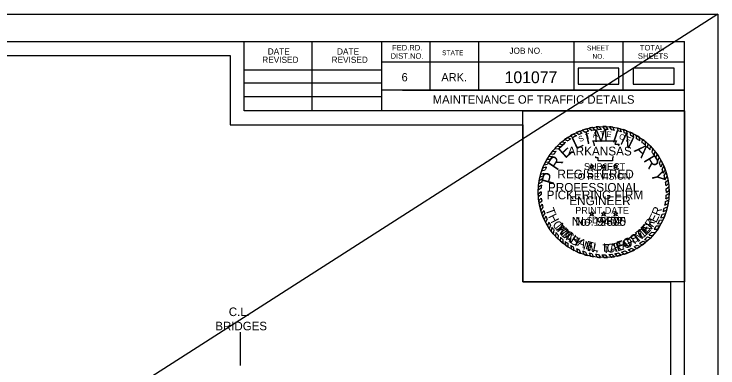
# Model space of a CAD drawing. Extents: x 13528 to 25043, y 7635 to 10612.
# Drawn here: x 22933 to 23433, y 10360 to 10612 of the extents above; entities that cross this region are included whole.
import ezdxf

# ---------------------------------------------------------------- set-up
doc = ezdxf.new("R2010")
doc.units = 0
for name, color, linetype in [('Default', 7, 'Continuous'), ('R_Border Notes', 7, 'Continuous'), ('R_Draft', 7, 'Continuous'), ('R_Revision Date Text', 7, 'Continuous'), ('STAMP_PE_CRAFTON', 7, 'Continuous'), ('STAMP_PE_FOSTER', 7, 'Continuous'), ('STAMP_PE_SEAL-INFO', 7, 'Continuous'), ('STAMP_PE_TAEGTMEYER', 7, 'Continuous'), ('STAMP_PE_TXT', 7, 'Continuous')]:
    doc.layers.add(name, color=color, linetype=linetype)

msp = doc.modelspace()

# ---------------------------------------------------------------- linework, layer by layer
at = {"layer": 'Default'}
for p, q in [((23433.27, 10611.55), (21766.57, 9544.86)), ((23093.63, 10361.47), (23093.63, 10385.3))]:
    msp.add_line(p, q, dxfattribs=at)
for points in [[(23333.73, 10561.6), (23362.89, 10561.6), (23362.89, 10573.15), (23333.73, 10573.15)], [(23372.93, 10561.6), (23402.09, 10561.6), (23402.09, 10573.15), (23372.93, 10573.15)]]:
    msp.add_lwpolyline(points, close=True, dxfattribs=at)
at = {"layer": 'R_Draft'}
for p, q in [((21828.61, 10592.07), (23409.51, 10592.07)), ((23096.31, 10542.67), (23096.31, 10592.07)), ((23144.71, 10542.67), (23144.71, 10592.07)), ((23194.01, 10592.07), (23194.01, 10542.67)), ((23228.21, 10592.07), (23228.21, 10557.37)), ((23262.91, 10592.07), (23262.91, 10557.37)), ((23330.81, 10592.07), (23330.81, 10557.37)), ((23365.51, 10592.07), (23365.51, 10557.37)), ((23409.51, 9564.77), (23409.51, 10592.07)), ((23409.51, 10577.37), (23194.01, 10577.37)), ((23409.51, 10577.47), (23409.51, 10577.47)), ((23096.31, 10571.97), (23194.01, 10571.97)), ((23096.31, 10562.67), (23194.01, 10562.67)), ((23409.51, 10557.37), (23194.01, 10557.37)), ((23208.81, 10557.37), (23409.51, 10557.37)), ((23096.31, 10552.97), (23194.01, 10552.97)), ((23409.51, 10542.67), (23096.31, 10542.67))]:
    msp.add_line(p, q, dxfattribs=at)
at = {"layer": 'R_Revision Date Text'}
for points in [[(21766.57, 10611.55), (23433.27, 10611.55), (23433.27, 9544.86), (21766.57, 9544.86)], [(23399.51, 10088.42), (21838.61, 10088.42), (21838.61, 10582.07), (23086.31, 10582.07), (23086.31, 10532.67), (23174.01, 10532.67), (23294.51, 10532.67), (23294.51, 10421.01), (23399.51, 10421.01)], [(21838.61, 10582.07), (23086.31, 10582.07), (23086.31, 10532.67), (23174.01, 10532.67), (23294.51, 10532.67), (23294.51, 10421.01), (23399.51, 10421.01), (23399.51, 9574.77), (21838.61, 9574.77)], [(23294.51, 10542.67), (23409.51, 10542.67), (23409.51, 10421.01), (23294.51, 10421.01)]]:
    msp.add_lwpolyline(points, close=True, dxfattribs=at)
at = {"layer": 'STAMP_PE_SEAL-INFO'}
for p, q in [((23341.7, 10530.35), (23343.48, 10528.63)), ((23344.11, 10530.83), (23345.61, 10528.99)), ((23346.69, 10531.19), (23348.1, 10529.28)), ((23350.37, 10529.42), (23348.81, 10531.39)), ((23352.86, 10529.45), (23351.46, 10531.5)), ((23355.15, 10529.34), (23353.86, 10531.46)), ((23357.68, 10529.09), (23356.21, 10531.31)), ((23359.8, 10528.77), (23358.52, 10531.04)), ((23362.62, 10528.17), (23361.75, 10530.47)), ((23330.37, 10526.17), (23332.69, 10525.05)), ((23332.53, 10527.23), (23334.48, 10525.86)), ((23335.07, 10528.31), (23336.54, 10526.68)), ((23336.81, 10528.95), (23338.71, 10527.42)), ((23339.76, 10529.86), (23341.2, 10528.12)), ((23364.62, 10527.63), (23363.83, 10529.98)), ((23366.88, 10526.9), (23366.18, 10529.29)), ((23368.97, 10526.1), (23368.25, 10528.58)), ((23371.28, 10525.07), (23370.77, 10527.56)), ((23373.51, 10523.92), (23373.07, 10526.47)), ((23375.45, 10522.79), (23375.25, 10525.29)), ((23322.21, 10520.73), (23324.86, 10520.23)), ((23324.1, 10522.37), (23326.38, 10521.34)), ((23326.2, 10523.7), (23328.41, 10522.69)), ((23328.13, 10524.92), (23330.29, 10523.81)), ((23344.37, 10521.34), (23361.09, 10521.34)), ((23344.98, 10519.81), (23344.37, 10521.34)), ((23361.09, 10521.34), (23359.97, 10518.88)), ((23377.62, 10521.36), (23377.46, 10523.93)), ((23379.42, 10520.02), (23379.59, 10522.46)), ((23381.66, 10518.16), (23381.75, 10520.78)), ((23317.2, 10515.89), (23319.81, 10515.7)), ((23318.82, 10517.61), (23321.54, 10517.41)), ((23320.49, 10519.23), (23322.79, 10518.54)), ((23345.5, 10518.32), (23344.98, 10519.81)), ((23345.54, 10517.75), (23345.5, 10518.32)), ((23359.97, 10518.88), (23363.13, 10518.88)), ((23363.13, 10518.88), (23362.41, 10517.75)), ((23383.22, 10516.7), (23383.56, 10519.19)), ((23385.01, 10514.83), (23385.35, 10517.46)), ((23386.38, 10513.25), (23387.06, 10515.61)), ((23312.91, 10510.27), (23315.49, 10510.44)), ((23314.08, 10511.99), (23316.61, 10511.96)), ((23315.48, 10513.84), (23318.22, 10513.95)), ((23346.49, 10509.2), (23346.36, 10510.29)), ((23358.68, 10510.29), (23358.29, 10508.74)), ((23388, 10511.17), (23388.68, 10513.66)), ((23389.1, 10509.59), (23389.99, 10511.91)), ((23310.53, 10506.15), (23313.02, 10506.47)), ((23311.68, 10508.26), (23314.13, 10508.36)), ((23348.06, 10509.2), (23346.49, 10509.2)), ((23348.06, 10507.05), (23348.06, 10509.2)), ((23358.21, 10507.05), (23348.06, 10507.05)), ((23358.29, 10508.74), (23358.21, 10507.05)), ((23390.64, 10507.1), (23391.56, 10509.56)), ((23391.64, 10505.27), (23392.77, 10507.49)), ((23392.79, 10502.85), (23393.93, 10505.28)), ((23307.92, 10500.01), (23310.34, 10500.69)), ((23308.67, 10502.04), (23311.19, 10502.77)), ((23309.59, 10504.2), (23312.1, 10504.72)), ((23393.5, 10501.17), (23394.82, 10503.33)), ((23394.47, 10498.42), (23395.82, 10500.79)), ((23306.61, 10495.46), (23308.96, 10496.42)), ((23307.13, 10497.49), (23309.52, 10498.34)), ((23395.01, 10496.6), (23396.48, 10498.86)), ((23395.67, 10493.8), (23397.27, 10496.04)), ((23308, 10491.93), (23305.77, 10490.82)), ((23308.43, 10494.22), (23306.1, 10492.98)), ((23396.02, 10491.9), (23397.79, 10493.67)), ((23396.35, 10489.36), (23398.21, 10491.04)), ((23307.53, 10487.63), (23305.42, 10486.34)), ((23307.71, 10489.75), (23305.52, 10488.35)), ((23396.51, 10487.27), (23398.46, 10488.73)), ((23396.58, 10484.68), (23398.6, 10486.29)), ((23307.44, 10485.16), (23305.42, 10483.48)), ((23307.48, 10483.13), (23305.52, 10481.5)), ((23307.64, 10480.65), (23305.79, 10478.87)), ((23396.32, 10480.12), (23398.49, 10481.4)), ((23396.52, 10482.65), (23398.61, 10484.04)), ((23307.9, 10478.5), (23306.13, 10476.64)), ((23308.29, 10476.21), (23306.6, 10474.37)), ((23395.62, 10475.68), (23397.89, 10476.66)), ((23396.07, 10478.18), (23398.28, 10479.28)), ((23308.76, 10474.11), (23307.2, 10472.04)), ((23309.38, 10471.88), (23307.91, 10469.79)), ((23394.34, 10470.95), (23396.79, 10471.95)), ((23395.08, 10473.42), (23397.43, 10474.43)), ((23310.09, 10469.76), (23308.68, 10467.7)), ((23310.92, 10467.63), (23309.61, 10465.52)), ((23311.78, 10465.71), (23310.64, 10463.41)), ((23392.6, 10466.48), (23395.04, 10466.96)), ((23393.67, 10469.05), (23396.08, 10469.7)), ((23312.95, 10463.42), (23312, 10460.97)), ((23314.13, 10461.4), (23313.21, 10459.05)), ((23389.57, 10460.9), (23391.96, 10460.87)), ((23390.43, 10462.3), (23392.94, 10462.57)), ((23391.79, 10464.8), (23394.23, 10465.14)), ((23315.14, 10459.85), (23314.59, 10457.09)), ((23316.54, 10457.89), (23316.04, 10455.24)), ((23318.06, 10456.01), (23317.63, 10453.41)), ((23386.33, 10456.46), (23388.64, 10456.06)), ((23387.87, 10458.43), (23390.4, 10458.44)), ((23319.58, 10454.32), (23319.27, 10451.71)), ((23321.19, 10452.69), (23321.04, 10450.05)), ((23322.91, 10451.13), (23322.89, 10448.48)), ((23381.12, 10451.14), (23383.47, 10450.49)), ((23383.14, 10453), (23385.35, 10452.31)), ((23384.42, 10454.29), (23386.8, 10453.87)), ((23324.71, 10449.66), (23324.8, 10447.03)), ((23326.4, 10448.41), (23326.58, 10445.82)), ((23328.54, 10447), (23328.84, 10444.44)), ((23330.29, 10445.97), (23330.75, 10443.4)), ((23373.67, 10445.94), (23375.75, 10444.77)), ((23375.74, 10447.16), (23377.99, 10446.18)), ((23377.46, 10448.3), (23379.65, 10447.35)), ((23379.76, 10450.01), (23382.1, 10449.29)), ((23332.7, 10444.72), (23333.48, 10442.11)), ((23334.56, 10443.88), (23335.42, 10441.32)), ((23337.02, 10442.91), (23338.07, 10440.41)), ((23339.07, 10442.24), (23340.2, 10439.79)), ((23341.61, 10441.55), (23342.67, 10439.22)), ((23343.6, 10441.12), (23344.83, 10438.83)), ((23346.1, 10440.71), (23347.3, 10438.51)), ((23348.28, 10440.47), (23349.65, 10438.33)), ((23350.7, 10440.34), (23352.22, 10438.27)), ((23353, 10440.33), (23354.72, 10438.35)), ((23355.6, 10440.46), (23357.22, 10438.56)), ((23357.79, 10440.69), (23359.65, 10438.9)), ((23360.01, 10441.04), (23361.95, 10439.35)), ((23362.47, 10441.56), (23364.36, 10439.94)), ((23364.77, 10442.19), (23366.85, 10440.7)), ((23367.24, 10443), (23369.45, 10441.66)), ((23369.33, 10443.82), (23371.45, 10442.52)), ((23371.63, 10444.87), (23374.05, 10443.81))]:
    msp.add_line(p, q, dxfattribs=at)
msp.add_circle((23352.01, 10484.89), 46.61, dxfattribs=at)
for radius, start, end in [(46.61, 99.7525, 102.7765), (46.61, 93.9381, 96.5517), (46.61, 87.7298, 90.6707), (46.61, 81.9732, 84.8236), (46.61, 75.3125, 77.9426), (46.61, 117.6544, 120.8099), (46.61, 111.3124, 114.7026), (44.57, 110.3086, 113.1659), (46.61, 105.2339, 109.0352), (44.57, 104.0352, 107.3615), (44.57, 98.258, 101.0329), (44.57, 92.1102, 95.0367), (44.57, 85.9628, 88.9097), (44.57, 79.9264, 82.696), (44.57, 73.5575, 76.2314), (46.61, 69.6061, 72.3058), (44.57, 67.6248, 70.504), (46.61, 63.1329, 66.2704), (46.61, 56.9003, 60.0942), (46.61, 129.7326, 132.5376), (46.61, 123.6199, 126.5906), (44.57, 121.9746, 125.11), (44.57, 115.6869, 119.1583), (44.57, 61.1558, 64.3784), (44.57, 54.9238, 58.2702), (46.61, 50.3492, 53.7159), (46.61, 135.4021, 138.3031), (44.57, 133.1331, 136.2562), (44.57, 127.5297, 130.9683), (44.57, 48.3016, 52.0395), (44.57, 42.2212, 45.5512), (46.61, 44.3405, 47.3929), (46.61, 38.1247, 41.2316), (46.61, 147.0072, 149.899), (46.61, 141.6056, 144.4486), (44.57, 145.0197, 148.2104), (44.57, 139.301, 142.5873), (44.57, 36.135, 39.5311), (46.61, 31.9614, 35.4294), (46.61, 152.864, 155.5189), (44.57, 151.0315, 153.573), (44.57, 29.9032, 33.6645), (44.57, 23.7732, 27.2211), (46.61, 25.9391, 29.0125), (46.61, 158.4077, 161.0701), (44.57, 156.3402, 159.2319), (44.57, 17.6802, 21.4251), (46.61, 19.9538, 23.3141), (46.61, 164.3068, 166.894), (44.57, 162.4331, 165.0013), (44.57, 11.5444, 15.2364), (46.61, 13.8421, 17.4447), (46.61, 170.0003, 172.6878), (44.57, 167.9048, 170.9039), (44.57, 5.7599, 9.0606), (46.61, 7.5852, 10.8621), (46.61, 175.7409, 178.2066), (44.57, 173.73, 176.4734), (44.57, 359.7329, 3.0639), (46.61, 1.7215, 4.7268), (46.61, 181.7251, 184.1626), (44.57, 179.6454, 182.2633), (44.57, 185.4539, 188.234), (44.57, 353.8632, 357.1274), (46.61, 355.7156, 358.9569), (46.61, 187.4204, 190.1927), (44.57, 191.2274, 193.9858), (44.57, 348.0778, 351.3435), (46.61, 349.8305, 353.0885), (46.61, 193.0369, 195.9973), (44.57, 196.9675, 199.8353), (44.57, 341.777, 345.0925), (46.61, 343.8925, 347.035), (46.61, 198.8967, 201.6281), (46.61, 204.5479, 207.4328), (44.57, 202.7761, 205.4791), (44.57, 335.6038, 339.1858), (46.61, 337.3837, 340.9933), (46.61, 210.8636, 213.6571), (44.57, 208.7883, 211.7934), (44.57, 323.5851, 327.4407), (46.61, 325.4405, 328.9872), (44.57, 329.5549, 333.2076), (46.61, 331.4037, 334.9332), (46.61, 216.6115, 219.491), (44.57, 214.1838, 217.2747), (44.57, 220.3909, 223.3056), (44.57, 316.6531, 320.3711), (46.61, 318.2846, 321.8043), (46.61, 222.48, 225.3801), (44.57, 226.2494, 229.2407), (44.57, 310.7744, 314.3161), (46.61, 312.4518, 315.6633), (46.61, 228.3665, 231.348), (44.57, 232.229, 234.9336), (46.61, 234.295, 236.9452), (44.57, 238.2223, 240.8353), (44.57, 299.0768, 302.1724), (46.61, 300.621, 303.8703), (44.57, 304.823, 308.5143), (46.61, 306.3721, 310.208), (46.61, 240.1977, 242.8613), (44.57, 244.3204, 246.9486), (46.61, 246.576, 249.1558), (44.57, 250.3491, 253.1216), (46.61, 252.5967, 255.3252), (44.57, 256.505, 259.1192), (44.57, 262.3783, 265.2012), (44.57, 268.3215, 271.277), (44.57, 274.6157, 277.4486), (44.57, 280.3459, 283.5814), (44.57, 286.6423, 289.9783), (46.61, 288.5709, 291.9733), (44.57, 292.8745, 296.1185), (46.61, 294.6481, 298.2166), (46.61, 258.4433, 261.1398), (46.61, 264.1978, 267.1009), (46.61, 270.2548, 273.3361), (46.61, 276.4239, 279.4357), (46.61, 282.3199, 285.3702)]:
    msp.add_arc((23352.01, 10484.89), radius, start, end, dxfattribs=at)
at = {"layer": 'STAMP_PE_TXT'}
for p, q in [((23342.91, 10502.74), (23341.91, 10503.46)), ((23341.91, 10503.46), (23343.14, 10503.46)), ((23342.53, 10501.58), (23342.91, 10502.74)), ((23343.52, 10502.3), (23342.53, 10501.58)), ((23343.14, 10503.46), (23343.52, 10504.63)), ((23343.52, 10504.63), (23343.9, 10503.46)), ((23344.51, 10501.58), (23343.52, 10502.3)), ((23343.9, 10503.46), (23345.12, 10503.46)), ((23345.12, 10503.46), (23344.13, 10502.74)), ((23344.13, 10502.74), (23344.51, 10501.58)), ((23351.4, 10502.74), (23350.4, 10503.46)), ((23350.4, 10503.46), (23351.63, 10503.46)), ((23351.02, 10501.58), (23351.4, 10502.74)), ((23352.01, 10502.3), (23351.02, 10501.58)), ((23351.63, 10503.46), (23352.01, 10504.63)), ((23352.01, 10504.63), (23352.39, 10503.46)), ((23353, 10501.58), (23352.01, 10502.3)), ((23352.39, 10503.46), (23353.61, 10503.46)), ((23353.61, 10503.46), (23352.62, 10502.74)), ((23352.62, 10502.74), (23353, 10501.58)), ((23359.89, 10502.74), (23358.89, 10503.46)), ((23358.89, 10503.46), (23360.12, 10503.46)), ((23359.51, 10501.58), (23359.89, 10502.74)), ((23360.5, 10502.3), (23359.51, 10501.58)), ((23360.12, 10503.46), (23360.5, 10504.63)), ((23360.5, 10504.63), (23360.88, 10503.46)), ((23361.49, 10501.58), (23360.5, 10502.3)), ((23360.88, 10503.46), (23362.1, 10503.46)), ((23362.1, 10503.46), (23361.11, 10502.74)), ((23361.11, 10502.74), (23361.49, 10501.58)), ((23343.14, 10469.93), (23343.52, 10471.09)), ((23343.52, 10471.09), (23343.9, 10469.93)), ((23351.63, 10469.93), (23352.01, 10471.09)), ((23352.01, 10471.09), (23352.39, 10469.93)), ((23360.12, 10469.93), (23360.5, 10471.09)), ((23360.5, 10471.09), (23360.88, 10469.93)), ((23342.91, 10469.21), (23341.91, 10469.93)), ((23341.91, 10469.93), (23343.14, 10469.93)), ((23342.53, 10468.04), (23342.91, 10469.21)), ((23343.52, 10468.76), (23342.53, 10468.04)), ((23344.51, 10468.04), (23343.52, 10468.76)), ((23343.9, 10469.93), (23345.12, 10469.93)), ((23345.12, 10469.93), (23344.13, 10469.21)), ((23344.13, 10469.21), (23344.51, 10468.04)), ((23351.4, 10469.21), (23350.4, 10469.93)), ((23350.4, 10469.93), (23351.63, 10469.93)), ((23351.02, 10468.04), (23351.4, 10469.21)), ((23352.01, 10468.76), (23351.02, 10468.04)), ((23353, 10468.04), (23352.01, 10468.76)), ((23352.39, 10469.93), (23353.61, 10469.93)), ((23353.61, 10469.93), (23352.62, 10469.21)), ((23352.62, 10469.21), (23353, 10468.04)), ((23359.89, 10469.21), (23358.89, 10469.93)), ((23358.89, 10469.93), (23360.12, 10469.93)), ((23359.51, 10468.04), (23359.89, 10469.21)), ((23360.5, 10468.76), (23359.51, 10468.04)), ((23361.49, 10468.04), (23360.5, 10468.76)), ((23360.88, 10469.93), (23362.1, 10469.93)), ((23362.1, 10469.93), (23361.11, 10469.21)), ((23361.11, 10469.21), (23361.49, 10468.04))]:
    msp.add_line(p, q, dxfattribs=at)

# ---------------------------------------------------------------- texts
at = {"layer": 'Default'}
for s, p in [('C.L. ', (23085.31, 10396.64)), ('BRIDGES', (23075.75, 10386.51))]:
    msp.add_text(s, height=6.1, dxfattribs=at).set_placement(p)
at = {"layer": 'R_Border Notes'}
for s, height, p in [('101077', 8.4, (23281.53, 10562.4)), ('MAINTENANCE OF TRAFFIC DETAILS', 6, (23230.35, 10547.77))]:
    msp.add_text(s, height=height, dxfattribs=at).set_placement(p)
at = {"layer": 'R_Draft'}
for s, height, p in [('DATE', 4.396, (23113, 10582.75)), ('DATE', 4.396, (23162.3, 10582.75)), ('FED.RD.', 3.91, (23201.41, 10585.67)), ('STATE', 3.42, (23237.01, 10582.27)), ('JOB NO.', 4.396, (23284.91, 10583.27)), ('SHEET', 3.42, (23340.11, 10585.67)), ('TOTAL', 3.91, (23377.71, 10585.67)), ('REVISED', 4.396, (23109.1, 10576.85)), ('REVISED', 4.396, (23158.4, 10576.85)), ('DIST.NO.', 3.91, (23200.41, 10579.77)), ('NO.', 3.42, (23344.01, 10579.77)), ('SHEETS', 3.91, (23376.31, 10579.77)), ('6', 5.86, (23208.21, 10563.67)), ('ARK.', 5.861, (23236.51, 10563.67))]:
    msp.add_text(s, height=height, dxfattribs=at).set_placement(p)
at = {"layer": 'STAMP_PE_CRAFTON'}
msp.add_text('No. 12370', height=6.25, dxfattribs=at).set_placement((23329.32, 10460.87))
for s, rotation, p in [('T', 310.7442, (23316.84, 10459.37)), ('N', 49.2411, (23383.42, 10455)), ('O', 317.6422, (23320.17, 10455.32)), ('N', 324.4537, (23324.4, 10451.39)), ('T', 34.1136, (23374.89, 10448.08)), ('O', 41.8391, (23379.18, 10451.09)), ('Y', 331.1686, (23329.57, 10447.81)), ('A', 20.5125, (23365.41, 10443.66)), ('F', 28.7821, (23370.31, 10445.53)), ('N', 347.4752, (23339.84, 10443.23)), ('C', 6.0117, (23354.37, 10441.59)), ('R', 14.8189, (23359.85, 10442.17)), ('.', 356.8926, (23345.99, 10441.85))]:
    msp.add_text(s, height=6.25, rotation=rotation, dxfattribs=at).set_placement(p)
at = {"layer": 'STAMP_PE_FOSTER'}
msp.add_text('No. 9402', height=6.25, dxfattribs=at).set_placement((23331.94, 10460.87))
for s, rotation, p in [('R', 54.5031, (23385.63, 10458.94)), ('M', 308.339, (23317.59, 10460)), ('E', 46.9613, (23382.01, 10454.84)), ('I', 314.1842, (23321.58, 10455.31)), ('C', 319.8733, (23323.35, 10453.54)), ('T', 39.4194, (23377.72, 10451.09)), ('H', 327.7235, (23327.99, 10449.86)), ('A', 335.7276, (23332.9, 10446.95)), ('E', 343.5779, (23338.59, 10444.6)), ('F', 15.8691, (23362.18, 10443.66)), ('O', 23.719, (23367.41, 10445.3)), ('S', 31.7234, (23372.96, 10447.95)), ('L', 350.8115, (23343.88, 10443.21)), ('L', 1.2666, (23351.58, 10442.43)), ('.', 6.8035, (23356.81, 10442.72))]:
    msp.add_text(s, height=6, rotation=rotation, dxfattribs=at).set_placement(p)
at = {"layer": 'STAMP_PE_SEAL-INFO'}
for s, rotation, p in [('I', 12.5248, (23339.7, 10518.82)), ('M', 3.1074, (23345.19, 10520.36)), ('I', 342.3164, (23357.53, 10520.7)), ('N', 333.9382, (23363.06, 10519.33)), ('L', 25.513, (23332.05, 10515.02)), ('E', 42.3578, (23324.64, 10508.37)), ('A', 315.6579, (23373.23, 10514.2)), ('R', 56.2292, (23318.86, 10499.7)), ('R', 301.3831, (23380.07, 10507.63)), ('Y', 283.2593, (23385.52, 10498.7)), ('P', 73.913, (23316.12, 10489.59))]:
    msp.add_text(s, height=9, rotation=rotation, dxfattribs=at).set_placement(p)
for s, height, p in [('SUBJECT', 4.8, (23338.01, 10500.63)), ('TO REVISION', 4.8, (23329.69, 10493.71)), ('PICKERING FIRM', 6.25, (23311.38, 10479.7)), ('PRINT DATE', 4.8, (23331.8, 10469.46)), ('$DATE$', 4.8, (23340.18, 10462.54))]:
    msp.add_text(s, height=height, dxfattribs=at).set_placement(p)
at = {"layer": 'STAMP_PE_TAEGTMEYER'}
for s, rotation, p in [('T', 289.646, (23310.48, 10472.44)), ('R', 69.57, (23391.73, 10467.46)), ('H', 296.7339, (23312.28, 10467.51)), ('Y', 53.9986, (23385.9, 10457.85)), ('E', 63.0984, (23389.24, 10462.55)), ('O', 303.7708, (23315.24, 10461.97)), ('M', 314.2033, (23318.52, 10457.22)), ('E', 46.8094, (23382.2, 10453.77)), ('A', 321.0594, (23323.33, 10452.4)), ('M', 39.3, (23377, 10449.38)), ('S', 327.8239, (23327.46, 10449.18)), ('G', 23.3052, (23367.01, 10444.2)), ('T', 31.466, (23372.51, 10446.66)), ('N', 344.2727, (23336.94, 10444.14)), ('T', 3.0061, (23351.33, 10441.49)), ('A', 8.9826, (23356.56, 10441.77)), ('E', 17.6836, (23361.76, 10442.54)), ('.', 350.6464, (23343.01, 10442.48))]:
    msp.add_text(s, height=6.25, rotation=rotation, dxfattribs=at).set_placement(p)
msp.add_text('No. 19605', height=6.25, dxfattribs=at).set_placement((23329.32, 10460.87))
at = {"layer": 'STAMP_PE_TXT'}
for s, rotation, p in [('T', 16.311, (23339.62, 10522.27)), ('A', 9.0679, (23344.43, 10523.53)), ('T', 1.8248, (23349.36, 10524.18)), ('E', 355.2002, (23353.91, 10524.22)), ('O', 342.2506, (23362.55, 10522.84)), ('S', 23.5541, (23335, 10520.4)), ('F', 335.0075, (23367.37, 10521.15))]:
    msp.add_text(s, height=3.91, rotation=rotation, dxfattribs=at).set_placement(p)
for s, p in [('ARKANSAS', (23326.47, 10510.94)), ('REGISTERED', (23319.09, 10494.59)), ('PROFESSIONAL', (23312.35, 10485.08)), ('ENGINEER', (23327.55, 10475.58))]:
    msp.add_text(s, height=6.25, dxfattribs=at).set_placement(p)

doc.saveas('drawing.dxf')
